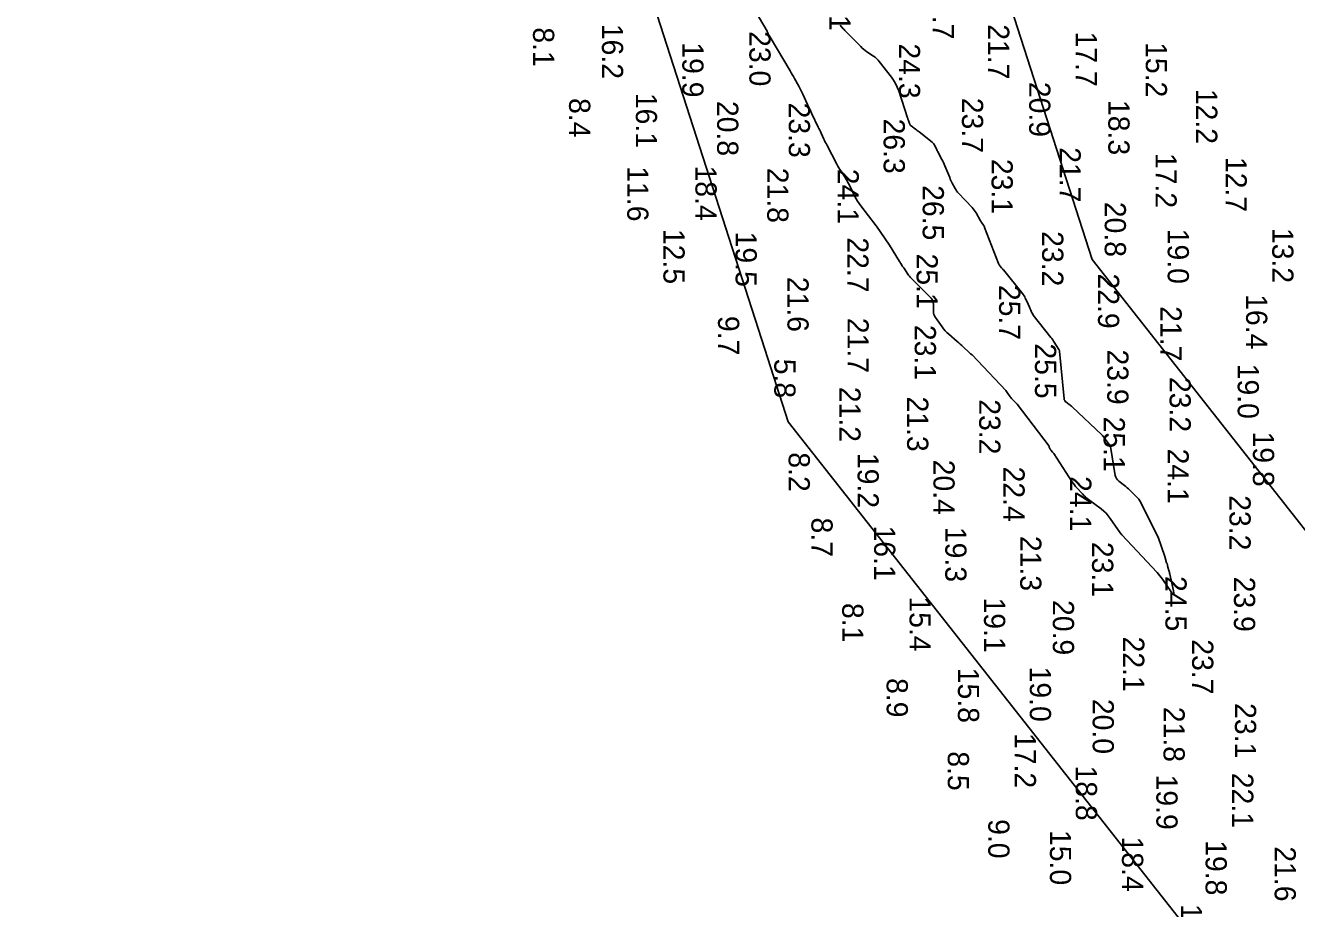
# Model space of a CAD drawing. Extents: x 1178573 to 1187098, y 693282 to 751751.
# Drawn here: x 1183256 to 1184005, y 738324 to 738845 of the extents above; entities that cross this region are included whole.
import ezdxf

# ---------------------------------------------------------------- set-up
doc = ezdxf.new("R2010")
doc.units = 0
for name, color, linetype in [('G-ANNO-PATT', 7, 'Continuous'), ('V-HYDS-MAJR', 7, 'Continuous'), ('V-HYDS-SOUN', 7, 'Continuous')]:
    doc.layers.add(name, color=color, linetype=linetype)

msp = doc.modelspace()

# ---------------------------------------------------------------- linework, layer by layer
at = {"layer": 'G-ANNO-PATT'}
msp.add_line((1184381.59, 738075.66), (1183884.78, 738706.45), dxfattribs=at)
for points in [[(1183884.78, 738706.45), (1183565.77, 739696.46), (1183463.01, 741660.48), (1183454.74, 741818.49), (1183255.55, 742478.87)], [(1183555.03, 739077.67), (1183691.64, 738653.74), (1183705.44, 738610.92), (1184201.87, 737980.6)], [(1183902.38, 738544.2), (1183901.39, 738545.29), (1183895.43, 738553.89), (1183894.26, 738555.44), (1183892.98, 738556.89), (1183891.59, 738558.24), (1183890.09, 738559.47), (1183882.67, 738565.12), (1183881.73, 738565.87), (1183880.82, 738566.66), (1183879.95, 738567.48), (1183879.12, 738568.35), (1183875.84, 738571.89), (1183875.05, 738572.79), (1183874.29, 738573.72), (1183873.57, 738574.68), (1183872.89, 738575.67), (1183862.13, 738592.14), (1183861.98, 738592.37), (1183861.82, 738592.59), (1183861.65, 738592.8), (1183861.47, 738593.01), (1183860.71, 738593.86), (1183860.55, 738594.05), (1183860.39, 738594.25), (1183860.25, 738594.46), (1183860.12, 738594.68), (1183859.6, 738595.56), (1183859.49, 738595.78), (1183859.43, 738596.01), (1183859.4, 738596.25), (1183859.41, 738596.5), (1183840.65, 738621.28), (1183840.14, 738621.71), (1183838.22, 738623.59), (1183837.75, 738624.07), (1183837.3, 738624.57), (1183836.87, 738625.08), (1183836.46, 738625.61), (1183834.66, 738628.06), (1183834.26, 738628.67), (1183833.94, 738629.31), (1183814.04, 738650.34), (1183813.06, 738650.95), (1183812.17, 738651.7), (1183808.74, 738655.03), (1183807.87, 738655.85), (1183806.99, 738656.66), (1183806.1, 738657.45), (1183805.2, 738658.23), (1183800.24, 738662.43), (1183799.14, 738663.42), (1183798.12, 738664.48), (1183797.16, 738665.59), (1183796.27, 738666.77), (1183792.32, 738672.37), (1183791.8, 738673.23), (1183791.44, 738674.13), (1183791.22, 738675.08), (1183791.16, 738676.08), (1183791.19, 738680.17), (1183791.1, 738681.15), (1183790.84, 738682.06), (1183790.39, 738682.9), (1183789.76, 738683.66), (1183778.13, 738695.39), (1183777.56, 738696), (1183777.01, 738696.64), (1183776.49, 738697.3), (1183776.01, 738697.99), (1183773.64, 738701.55), (1183773.42, 738701.87), (1183773.21, 738702.19), (1183773, 738702.51), (1183772.79, 738702.84), (1183771.95, 738704.14), (1183771.74, 738704.47), (1183771.53, 738704.79), (1183771.32, 738705.12), (1183771.12, 738705.45), (1183765.23, 738714.93), (1183757.62, 738726.14), (1183757.34, 738726.45), (1183748.27, 738738.18), (1183747.31, 738739.49), (1183746.42, 738740.84), (1183745.59, 738742.24), (1183744.84, 738743.68), (1183741.61, 738750.3), (1183741.06, 738751.37), (1183740.49, 738752.42), (1183739.89, 738753.46), (1183739.25, 738754.48), (1183736.66, 738758.53), (1183736.03, 738759.55), (1183735.41, 738760.58), (1183734.82, 738761.62), (1183734.25, 738762.68), (1183728.25, 738774.07), (1183727.81, 738774.93), (1183727.37, 738775.8), (1183726.94, 738776.68), (1183726.53, 738777.55), (1183724.88, 738781.08), (1183724.47, 738781.96), (1183724.06, 738782.84), (1183723.64, 738783.71), (1183723.22, 738784.59), (1183719.51, 738792.34), (1183718.84, 738793.74), (1183718.18, 738795.15), (1183717.53, 738796.56), (1183716.89, 738797.97), (1183714.13, 738804.07), (1183713.58, 738805.25), (1183713.01, 738806.42), (1183712.41, 738807.58), (1183711.78, 738808.73), (1183709.22, 738813.28), (1183708.58, 738814.42), (1183707.93, 738815.55), (1183707.28, 738816.68), (1183706.62, 738817.81), (1183694.32, 738838.65), (1183694.27, 738838.74), (1183694.22, 738838.82), (1183694.17, 738838.9), (1183694.11, 738838.98), (1183693.89, 738839.3), (1183693.83, 738839.38), (1183693.78, 738839.46), (1183693.73, 738839.55), (1183693.69, 738839.63), (1183693.24, 738840.55), (1183693.16, 738840.73), (1183693.09, 738840.92), (1183693.04, 738841.12), (1183679.02, 738865.37)], [(1183736.06, 738844.7), (1183737.98, 738842.61), (1183738.47, 738842.09), (1183738.95, 738841.58), (1183739.44, 738841.06), (1183739.94, 738840.56), (1183748.27, 738832.06), (1183749.11, 738831.24), (1183750, 738830.47), (1183750.92, 738829.74), (1183751.89, 738829.06), (1183755.82, 738826.45), (1183756.77, 738825.76), (1183757.66, 738825), (1183758.48, 738824.17), (1183759.24, 738823.28), (1183766.35, 738814.13), (1183767.69, 738812.25), (1183768.86, 738810.27), (1183769.85, 738808.2), (1183770.66, 738806.04), (1183775.87, 738790.14), (1183776.02, 738789.71), (1183776.16, 738789.27), (1183776.3, 738788.84), (1183776.45, 738788.41), (1183777.03, 738786.67), (1183777.21, 738786.26), (1183777.44, 738785.89), (1183777.72, 738785.56), (1183778.06, 738785.27), (1183780.56, 738783.44), (1183781.09, 738783.04), (1183781.63, 738782.64), (1183782.16, 738782.23), (1183782.68, 738781.82), (1183790.44, 738775.7), (1183790.88, 738775.31), (1183791.27, 738774.88), (1183791.61, 738774.4), (1183791.89, 738773.89), (1183792.92, 738771.74), (1183793.18, 738771.2), (1183793.45, 738770.67), (1183793.72, 738770.14), (1183793.99, 738769.61), (1183796.19, 738765.41), (1183796.64, 738764.53), (1183797.07, 738763.64), (1183797.48, 738762.74), (1183797.86, 738761.83), (1183800.76, 738754.81), (1183801.1, 738753.99), (1183801.47, 738753.19), (1183801.85, 738752.4), (1183802.26, 738751.61), (1183803.91, 738748.48), (1183804.35, 738747.72), (1183804.84, 738746.99), (1183805.38, 738746.3), (1183805.96, 738745.64), (1183814, 738737.17), (1183814.66, 738736.42), (1183815.28, 738735.64), (1183815.86, 738734.82), (1183816.38, 738733.97), (1183819, 738729.42), (1183819.19, 738729.08), (1183819.4, 738728.75), (1183819.6, 738728.42), (1183819.81, 738728.09), (1183820.66, 738726.78), (1183820.86, 738726.45), (1183821.05, 738726.11), (1183821.21, 738725.76), (1183821.36, 738725.4), (1183829.61, 738704.19), (1183829.77, 738703.83), (1183829.95, 738703.48), (1183830.16, 738703.15), (1183830.4, 738702.84), (1183831.41, 738701.6), (1183831.66, 738701.29), (1183831.91, 738700.99), (1183832.16, 738700.68), (1183832.41, 738700.37), (1183843.7, 738686.45), (1183844.17, 738685.83), (1183844.6, 738685.19), (1183844.99, 738684.52), (1183845.34, 738683.82), (1183846.78, 738680.76), (1183847.05, 738680.18), (1183847.31, 738679.59), (1183847.57, 738679), (1183847.82, 738678.4), (1183848.8, 738676.02), (1183849.06, 738675.43), (1183849.36, 738674.87), (1183849.71, 738674.33), (1183850.08, 738673.81), (1183860.47, 738660.61), (1183861.01, 738659.92), (1183861.52, 738659.2), (1183862.01, 738658.48), (1183862.48, 738657.74), (1183865.18, 738653.38), (1183865.21, 738653.32), (1183865.25, 738653.25), (1183865.28, 738653.19), (1183865.31, 738653.12), (1183865.44, 738652.84), (1183865.46, 738652.77), (1183865.49, 738652.7), (1183865.5, 738652.63), (1183865.51, 738652.56), (1183868.26, 738624.39), (1183868.37, 738623.84), (1183868.58, 738623.34), (1183868.9, 738622.91), (1183869.31, 738622.53), (1183871.19, 738621.13), (1183871.66, 738620.78), (1183872.11, 738620.41), (1183872.55, 738620.03), (1183872.99, 738619.64), (1183890.59, 738603.2), (1183890.91, 738602.81), (1183895.12, 738597.36), (1183895.46, 738596.89), (1183895.65, 738596.26), (1183898.46, 738579.23), (1183898.71, 738578.23), (1183899.14, 738577.34), (1183899.73, 738576.54), (1183900.49, 738575.85), (1183903.86, 738573.28), (1183904.69, 738572.63), (1183905.5, 738571.94), (1183906.28, 738571.23), (1183907.04, 738570.49), (1183912.32, 738565.15), (1183912.97, 738564.29)], [(1183912.97, 738564.29), (1183923.78, 738542.82), (1183927.67, 738531.42), (1183928.7, 738527.75), (1183928.96, 738527.31), (1183929.41, 738525.18), (1183930.06, 738523.16), (1183930.21, 738522.65), (1183930.36, 738522.14), (1183930.49, 738521.62), (1183930.61, 738521.1), (1183932.75, 738511.24), (1183932.96, 738509.85), (1183932.81, 738509.28), (1183932.29, 738509.55), (1183931.41, 738510.66), (1183926.22, 738518.1), (1183925.5, 738519.1), (1183924.74, 738520.08), (1183923.96, 738521.04), (1183923.15, 738521.97), (1183902.38, 738544.2)]]:
    msp.add_lwpolyline(points, dxfattribs=at)
at = {"layer": 'V-HYDS-MAJR'}
for points in [[(1183902.38, 738544.2), (1183901.39, 738545.29), (1183895.43, 738553.89), (1183894.26, 738555.44), (1183892.98, 738556.89), (1183891.59, 738558.24), (1183890.09, 738559.47), (1183882.67, 738565.12), (1183881.73, 738565.87), (1183880.82, 738566.66), (1183879.95, 738567.48), (1183879.12, 738568.35), (1183875.84, 738571.89), (1183875.05, 738572.79), (1183874.29, 738573.72), (1183873.57, 738574.68), (1183872.89, 738575.67), (1183862.13, 738592.14), (1183861.98, 738592.37), (1183861.82, 738592.59), (1183861.65, 738592.8), (1183861.47, 738593.01), (1183860.71, 738593.86), (1183860.55, 738594.05), (1183860.39, 738594.25), (1183860.25, 738594.46), (1183860.12, 738594.68), (1183859.6, 738595.56), (1183859.49, 738595.78), (1183859.43, 738596.01), (1183859.4, 738596.25), (1183859.41, 738596.5), (1183840.65, 738621.28), (1183840.14, 738621.71), (1183838.22, 738623.59), (1183837.75, 738624.07), (1183837.3, 738624.57), (1183836.87, 738625.08), (1183836.46, 738625.61), (1183834.66, 738628.06), (1183834.26, 738628.67), (1183833.94, 738629.31), (1183814.04, 738650.34), (1183813.06, 738650.95), (1183812.17, 738651.7), (1183808.74, 738655.03), (1183807.87, 738655.85), (1183806.99, 738656.66), (1183806.1, 738657.45), (1183805.2, 738658.23), (1183800.24, 738662.43), (1183799.14, 738663.42), (1183798.12, 738664.48), (1183797.16, 738665.59), (1183796.27, 738666.77), (1183792.32, 738672.37), (1183791.8, 738673.23), (1183791.44, 738674.13), (1183791.22, 738675.08), (1183791.16, 738676.08), (1183791.19, 738680.17), (1183791.1, 738681.15), (1183790.84, 738682.06), (1183790.39, 738682.9), (1183789.76, 738683.66), (1183778.13, 738695.39), (1183777.56, 738696), (1183777.01, 738696.64), (1183776.49, 738697.3), (1183776.01, 738697.99), (1183773.64, 738701.55), (1183773.42, 738701.87), (1183773.21, 738702.19), (1183773, 738702.51), (1183772.79, 738702.84), (1183771.95, 738704.14), (1183771.74, 738704.47), (1183771.53, 738704.79), (1183771.32, 738705.12), (1183771.12, 738705.45), (1183765.23, 738714.93), (1183757.62, 738726.14), (1183757.34, 738726.45), (1183748.27, 738738.18), (1183747.31, 738739.49), (1183746.42, 738740.84), (1183745.59, 738742.24), (1183744.84, 738743.68), (1183741.61, 738750.3), (1183741.06, 738751.37), (1183740.49, 738752.42), (1183739.89, 738753.46), (1183739.25, 738754.48), (1183736.66, 738758.53), (1183736.03, 738759.55), (1183735.41, 738760.58), (1183734.82, 738761.62), (1183734.25, 738762.68), (1183728.25, 738774.07), (1183727.81, 738774.93), (1183727.37, 738775.8), (1183726.94, 738776.68), (1183726.53, 738777.55), (1183724.88, 738781.08), (1183724.47, 738781.96), (1183724.06, 738782.84), (1183723.64, 738783.71), (1183723.22, 738784.59), (1183719.51, 738792.34), (1183718.84, 738793.74), (1183718.18, 738795.15), (1183717.53, 738796.56), (1183716.89, 738797.97), (1183714.13, 738804.07), (1183713.58, 738805.25), (1183713.01, 738806.42), (1183712.41, 738807.58), (1183711.78, 738808.73), (1183709.22, 738813.28), (1183708.58, 738814.42), (1183707.93, 738815.55), (1183707.28, 738816.68), (1183706.62, 738817.81), (1183694.32, 738838.65), (1183694.27, 738838.74), (1183694.22, 738838.82), (1183694.17, 738838.9), (1183694.11, 738838.98), (1183693.89, 738839.3), (1183693.83, 738839.38), (1183693.78, 738839.46), (1183693.73, 738839.55), (1183693.69, 738839.63), (1183693.24, 738840.55), (1183693.16, 738840.73), (1183693.09, 738840.92), (1183693.04, 738841.12), (1183679.02, 738865.37)], [(1183736.06, 738844.7), (1183737.98, 738842.61), (1183738.47, 738842.09), (1183738.95, 738841.58), (1183739.44, 738841.06), (1183739.94, 738840.56), (1183748.27, 738832.06), (1183749.11, 738831.24), (1183750, 738830.47), (1183750.92, 738829.74), (1183751.89, 738829.06), (1183755.82, 738826.45), (1183756.77, 738825.76), (1183757.66, 738825), (1183758.48, 738824.17), (1183759.24, 738823.28), (1183766.35, 738814.13), (1183767.69, 738812.25), (1183768.86, 738810.27), (1183769.85, 738808.2), (1183770.66, 738806.04), (1183775.87, 738790.14), (1183776.02, 738789.71), (1183776.16, 738789.27), (1183776.3, 738788.84), (1183776.45, 738788.41), (1183777.03, 738786.67), (1183777.21, 738786.26), (1183777.44, 738785.89), (1183777.72, 738785.56), (1183778.06, 738785.27), (1183780.56, 738783.44), (1183781.09, 738783.04), (1183781.63, 738782.64), (1183782.16, 738782.23), (1183782.68, 738781.82), (1183790.44, 738775.7), (1183790.88, 738775.31), (1183791.27, 738774.88), (1183791.61, 738774.4), (1183791.89, 738773.89), (1183792.92, 738771.74), (1183793.18, 738771.2), (1183793.45, 738770.67), (1183793.72, 738770.14), (1183793.99, 738769.61), (1183796.19, 738765.41), (1183796.64, 738764.53), (1183797.07, 738763.64), (1183797.48, 738762.74), (1183797.86, 738761.83), (1183800.76, 738754.81), (1183801.1, 738753.99), (1183801.47, 738753.19), (1183801.85, 738752.4), (1183802.26, 738751.61), (1183803.91, 738748.48), (1183804.35, 738747.72), (1183804.84, 738746.99), (1183805.38, 738746.3), (1183805.96, 738745.64), (1183814, 738737.17), (1183814.66, 738736.42), (1183815.28, 738735.64), (1183815.86, 738734.82), (1183816.38, 738733.97), (1183819, 738729.42), (1183819.19, 738729.08), (1183819.4, 738728.75), (1183819.6, 738728.42), (1183819.81, 738728.09), (1183820.66, 738726.78), (1183820.86, 738726.45), (1183821.05, 738726.11), (1183821.21, 738725.76), (1183821.36, 738725.4), (1183829.61, 738704.19), (1183829.77, 738703.83), (1183829.95, 738703.48), (1183830.16, 738703.15), (1183830.4, 738702.84), (1183831.41, 738701.6), (1183831.66, 738701.29), (1183831.91, 738700.99), (1183832.16, 738700.68), (1183832.41, 738700.37), (1183843.7, 738686.45), (1183844.17, 738685.83), (1183844.6, 738685.19), (1183844.99, 738684.52), (1183845.34, 738683.82), (1183846.78, 738680.76), (1183847.05, 738680.18), (1183847.31, 738679.59), (1183847.57, 738679), (1183847.82, 738678.4), (1183848.8, 738676.02), (1183849.06, 738675.43), (1183849.36, 738674.87), (1183849.71, 738674.33), (1183850.08, 738673.81), (1183860.47, 738660.61), (1183861.01, 738659.92), (1183861.52, 738659.2), (1183862.01, 738658.48), (1183862.48, 738657.74), (1183865.18, 738653.38), (1183865.21, 738653.32), (1183865.25, 738653.25), (1183865.28, 738653.19), (1183865.31, 738653.12), (1183865.44, 738652.84), (1183865.46, 738652.77), (1183865.49, 738652.7), (1183865.5, 738652.63), (1183865.51, 738652.56), (1183868.26, 738624.39), (1183868.37, 738623.84), (1183868.58, 738623.34), (1183868.9, 738622.91), (1183869.31, 738622.53), (1183871.19, 738621.13), (1183871.66, 738620.78), (1183872.11, 738620.41), (1183872.55, 738620.03), (1183872.99, 738619.64), (1183890.59, 738603.2), (1183890.91, 738602.81), (1183895.12, 738597.36), (1183895.46, 738596.89), (1183895.65, 738596.26), (1183898.46, 738579.23), (1183898.71, 738578.23), (1183899.14, 738577.34), (1183899.73, 738576.54), (1183900.49, 738575.85), (1183903.86, 738573.28), (1183904.69, 738572.63), (1183905.5, 738571.94), (1183906.28, 738571.23), (1183907.04, 738570.49), (1183912.32, 738565.15), (1183912.97, 738564.29)], [(1183912.97, 738564.29), (1183923.78, 738542.82), (1183927.67, 738531.42), (1183928.7, 738527.75), (1183928.96, 738527.31), (1183929.41, 738525.18), (1183930.06, 738523.16), (1183930.21, 738522.65), (1183930.36, 738522.14), (1183930.49, 738521.62), (1183930.61, 738521.1), (1183932.75, 738511.24), (1183932.96, 738509.85), (1183932.81, 738509.28), (1183932.29, 738509.55), (1183931.41, 738510.66), (1183926.22, 738518.1), (1183925.5, 738519.1), (1183924.74, 738520.08), (1183923.96, 738521.04), (1183923.15, 738521.97), (1183902.38, 738544.2)]]:
    msp.add_lwpolyline(points, dxfattribs=at)

# ---------------------------------------------------------------- texts
at = {"layer": 'V-HYDS-SOUN'}
for s, p in [('25.1 ', (1183729.76, 738873.92)), ('22.7 ', (1183790.74, 738868.88)), ('8.1', (1183554.99, 738843.43)), ('16.2 ', (1183595.62, 738845.51)), ('23.0 ', (1183682.6, 738841.19)), ('21.7 ', (1183823.41, 738845.25)), ('17.7 ', (1183875.15, 738840.96)), ('19.9 ', (1183643.04, 738834.59)), ('24.3 ', (1183770.79, 738833.93)), ('15.2 ', (1183916.45, 738834.72)), ('20.9 ', (1183847.64, 738811.3)), ('8.4', (1183576.25, 738801.73)), ('16.1 ', (1183615.62, 738804.83)), ('23.7 ', (1183807.99, 738801.91)), ('12.2 ', (1183946.11, 738807.19)), ('20.8 ', (1183663.58, 738800.04)), ('23.3 ', (1183705.86, 738799.06)), ('18.3 ', (1183894.35, 738800.6)), ('26.3 ', (1183761.8, 738789.64)), ('21.7 ', (1183865.57, 738772.75)), ('23.1 ', (1183825.46, 738765.88)), ('17.2 ', (1183922.16, 738769.36)), ('12.7 ', (1183963.51, 738767)), ('11.6 ', (1183610.55, 738761.49)), ('18.4 ', (1183650.78, 738761.96)), ('21.8 ', (1183693.14, 738760.64)), ('24.1 ', (1183734.65, 738760.04)), ('26.5 ', (1183784.84, 738750.38)), ('20.8 ', (1183892.22, 738740.56)), ('12.5 ', (1183631.89, 738724.56)), ('19.5 ', (1183674.47, 738722.96)), ('22.7 ', (1183740.38, 738719.6)), ('23.2 ', (1183855.29, 738723.27)), ('19.0 ', (1183929.35, 738724.69)), ('13.2 ', (1183991.02, 738725.17)), ('25.1 ', (1183781.24, 738710.04)), ('21.6 ', (1183705.04, 738696.37)), ('22.9 ', (1183888.25, 738698.3)), ('25.7 ', (1183829.91, 738691.58)), ('16.4 ', (1183975.61, 738686.11)), ('21.7 ', (1183925.09, 738679.05)), ('9.7', (1183664.11, 738673.28)), ('21.7 ', (1183740.48, 738672.16)), ('23.1 ', (1183780.15, 738668.01)), ('25.5 ', (1183851.08, 738657.08)), ('23.9 ', (1183893.7, 738653.49)), ('5.8', (1183697.31, 738648.03)), ('19.0 ', (1183970.63, 738645.1)), ('23.2 ', (1183930.46, 738637.31)), ('21.2 ', (1183735.68, 738631.5)), ('21.3 ', (1183775.65, 738625.76)), ('23.2 ', (1183818.16, 738624.12)), ('25.1 ', (1183891.6, 738613.91)), ('19.8 ', (1183979.63, 738605.13)), ('8.2', (1183705.77, 738592.86)), ('19.2 ', (1183746.44, 738592.5)), ('24.1 ', (1183929.27, 738595.05)), ('20.4 ', (1183791.16, 738588.5)), ('22.4 ', (1183832.47, 738584.44)), ('24.1 ', (1183871.82, 738578.84)), ('23.2 ', (1183965.79, 738567.56)), ('8.7', (1183719.19, 738554.41)), ('16.1 ', (1183756.2, 738549.71)), ('19.3 ', (1183798.15, 738548.9)), ('21.3 ', (1183842.35, 738543.58)), ('23.1 ', (1183884.75, 738540.06)), ('24.5 ', (1183928.02, 738519.9)), ('23.9 ', (1183968.44, 738519.53)), ('8.1', (1183737.37, 738504.02)), ('15.4 ', (1183777.06, 738507.9)), ('19.1 ', (1183821, 738507.25)), ('20.9 ', (1183861.61, 738505.75)), ('22.1 ', (1183903.05, 738484.22)), ('23.7 ', (1183943.76, 738482.62)), ('15.8 ', (1183805.64, 738465.82)), ('19.0 ', (1183848.02, 738466.49)), ('8.9', (1183763.58, 738459.74)), ('20.0 ', (1183885.09, 738447.49)), ('21.8 ', (1183926.9, 738442.82)), ('23.1 ', (1183969.03, 738445.02)), ('17.2 ', (1183839.15, 738427.34)), ('8.5', (1183799.64, 738416.57)), ('18.8 ', (1183875.16, 738408.18)), ('22.1 ', (1183967.36, 738403.91)), ('19.9 ', (1183922.67, 738402.83)), ('9.0', (1183823.52, 738376.56)), ('15.0 ', (1183859.9, 738370.16)), ('18.4 ', (1183902.42, 738366.33)), ('19.8 ', (1183951.71, 738364.15)), ('21.6 ', (1183992.44, 738360.54)), ('18.5 ', (1183937.17, 738326.5))]:
    msp.add_text(s, height=12.5, rotation=270, dxfattribs=at).set_placement(p)

doc.saveas('drawing.dxf')
